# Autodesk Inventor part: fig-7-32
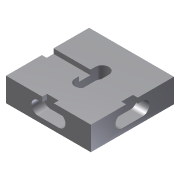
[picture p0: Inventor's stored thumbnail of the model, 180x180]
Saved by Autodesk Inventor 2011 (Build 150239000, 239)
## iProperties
Created: 2004-05
Part Number: fig-7-32
Document SubType Name: Modeling
Designer: CADCIM Technologies
Manufacturer: Standard
Standards Organization: Custom
Density: 1 g/cm^3
Author: CADCIM Technologies
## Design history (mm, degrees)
sketch "Sketch1"
  geometry: L1 (-30.233, -25.517)-(22.302, -25.517); L2 (22.302, -25.517)-(22.302, 25.904); L3 (22.302, 25.904)-(-30.233, 25.904); L4 (-30.233, 25.904)-(-30.233, -25.517)
  constraints: 8 end point, 2 parallel, 1 horizontal, 1 perpendicular
extrude "Extrusion1" new body sketch "Sketch1" distance "d0" = 14.75; taper "d1" = 0 deg
sketch "Sketch2"
  geometry: L1 (1.047, -5.75)-(1.047, 6.846); L2 (-7.35, 6.845)-(-7.35, -5.75); A1 r 4.198 centre (-3.152, 6.846) between (1.047, 6.846) and (-7.35, 6.845); A2 r 4.198 centre (-3.152, -5.75) between (-7.35, -5.75) and (1.047, -5.75)
  constraints: 4 end point, 4 point on circle, 4 tangent, 2 centre point, 1 parallel
extrude "Extrusion2" cut sketch "Sketch2" distance "d2" = 7.5; taper "d3" = 0 deg
sketch "Sketch3"
  geometry: L1 (-7.5, 0)-(-7.5, 12.595) reference; L2 (-7.5, 0)-(0, 0) reference; L3 (-7.5, 2.416)-(-4.537, 2.416); L4 (-4.537, 2.416)-(-4.537, 9.616); L5 (-4.537, 9.616)-(-7.5, 9.616)
  constraints: 6 end point, 2 perpendicular, 2 point on line, 1 parallel
extrude "Extrusion3" cut sketch "Sketch3" stored distance "d4" = 6.75; taper "d5" = 0 deg
sketch "Sketch4"
  geometry: L1 (1.047, -5.75)-(1.047, 6.846); L2 (-7.35, 6.845)-(-7.35, -5.75); A1 r 4.198 centre (-3.152, 6.846) between (1.047, 6.846) and (-7.35, 6.845); A2 r 4.198 centre (-3.152, -5.75) between (-7.35, -5.75) and (1.047, -5.75)
  constraints: 4 end point, 4 point on circle, 4 tangent, 2 centre point, 1 parallel
extrude "Extrusion4" cut sketch "Sketch4" taper "d7" = 0 deg; distance "d8" = 7.5
sketch "Sketch5"
  geometry: L1 (-7.5, 0)-(-7.5, 12.595) reference; L2 (-7.5, 0)-(0, 0) reference; L3 (-7.5, 2.416)-(-4.537, 2.416); L4 (-4.537, 2.416)-(-4.537, 9.616); L5 (-4.537, 9.616)-(-7.5, 9.616)
  constraints: 6 end point, 2 perpendicular, 2 point on line, 1 parallel
extrude "Extrusion5" cut sketch "Sketch5" taper "d10" = 0 deg; stored distance "d11" = 6.75
sketch "Sketch6"
  geometry: L1 (1.047, -5.75)-(1.047, 6.846); L2 (-7.35, 6.845)-(-7.35, -5.75); A1 r 4.198 centre (-3.152, 6.846) between (1.047, 6.846) and (-7.35, 6.845); A2 r 4.198 centre (-3.152, -5.75) between (-7.35, -5.75) and (1.047, -5.75)
  constraints: 4 end point, 4 point on circle, 4 tangent, 2 centre point, 1 parallel
extrude "Extrusion6" cut sketch "Sketch6" taper "d13" = 0 deg; distance "d14" = 7.5
sketch "Sketch7"
  geometry: L1 (-7.5, 0)-(-7.5, 12.595) reference; L2 (-7.5, 0)-(0, 0) reference; L3 (-7.5, 2.416)-(-4.537, 2.416); L4 (-4.537, 2.416)-(-4.537, 9.616); L5 (-4.537, 9.616)-(-7.5, 9.616)
  constraints: 6 end point, 2 perpendicular, 2 point on line, 1 parallel
extrude "Extrusion7" cut sketch "Sketch7" taper "d16" = 0 deg; stored distance "d17" = 6.75
body "Solid1"
